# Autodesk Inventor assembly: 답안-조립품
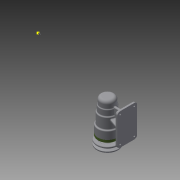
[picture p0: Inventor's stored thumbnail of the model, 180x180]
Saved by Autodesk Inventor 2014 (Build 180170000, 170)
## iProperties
Created: 2016-06
Part Number: 답안-조립품
Document SubType Name: Assembly
Designer: SEC
Author: SEC
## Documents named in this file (12)
- C:\Documents and Settings\SEC\바탕 화면\460607V1006\답안-조립품.iam
- C:\Documents and Settings\SEC\바탕 화면\460607V1006\본체.ipt
- C:\Documents and Settings\SEC\바탕 화면\460607V1006\커버.ipt
- C:\Documents and Settings\SEC\바탕 화면\460607V1006\축.ipt
- C:\Documents and Settings\SEC\바탕 화면\460607V1006\키 5 x 5 x 16.ipt
- C:\Documents and Settings\SEC\바탕 화면\460607V1006\V벨트풀리.ipt
- C:\Documents and Settings\SEC\바탕 화면\460607V1006\베어링 6004.ipt
- C:\Documents and Settings\SEC\바탕 화면\460607V1006\오일 실.ipt
- C:\Documents and Settings\SEC\바탕 화면\460607V1006\멈춤나사 M3x8.ipt
- C:\Documents and Settings\SEC\바탕 화면\460607V1006\어댑터슬리브.ipt
- C:\Documents and Settings\SEC\바탕 화면\460607V1006\베어링 51202.ipt
- C:\Documents and Settings\SEC\바탕 화면\460607V1006\볼트 M4 x 12.ipt
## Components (6 placed, 2 different names)
1. V벨트풀리:1 — 플러쉬:1, 각도:1
2. ISO 4762 M4 x 12:1 — 각도:1
3. ISO 4762 M4 x 12:2 — 각도:2
4. ISO 4762 M4 x 12:3
5. ISO 4762 M4 x 12:4
6. ISO 4762 M4 x 12:5
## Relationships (3: Angle 2, Flush 1)
- 플러쉬:1 [Flush]: V벨트풀리:1
- 각도:1 [Angle]: V벨트풀리:1 ↔ ISO 4762 M4 x 12:1
- 각도:2 [Angle]: ISO 4762 M4 x 12:2
